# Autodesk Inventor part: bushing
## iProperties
Title: bushing
Subject: Boston Gear bronze bushing
Author: sbraun
Comments: Boston Gear oil impregnated bronze bushings "Bost-Bronz" series pg 11-13
Shininess: 20.0
PropertySet Name: _Private Model Information
Created: 2001-02
Part Number: Bronze Bushing
Material: Bronze, Soft Tin
Document SubType Name: Modeling
Designer: sbraun
Control State: 0
Master: False
Checked Out: False
PropertySet Name: Design Tracking Control
Density: 8.874
Volumn: 0.07541232403755735
Area: 1.425114784961713
PropertySet Name: Model Information
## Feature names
1. Extrusion1
